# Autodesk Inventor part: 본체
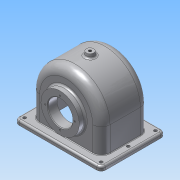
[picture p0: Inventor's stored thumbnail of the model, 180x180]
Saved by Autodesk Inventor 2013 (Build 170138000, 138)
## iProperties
Created: 2015-09
Part Number: 본체
Material: 알루미늄 6061
Document SubType Name: Modeling
Designer: Administrator
Density: 2.71 g/cm^3
Mass: 723.133 g
Surface Area: 889.936 cm^2
Volume: 266.839 cm^3
Author: Administrator
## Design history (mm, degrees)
sketch "스케치1"
  geometry: L1 (-52, 70)-(52, 70); L2 (52, 70)-(52, -70); L3 (52, -70)-(-52, -70); L4 (-52, -70)-(-52, 70); 3 further points
  constraints: 8 end point, 2 midpoint, 2 parallel, 1 horizontal, 1 horizontal alignment, 1 perpendicular, 1 vertical alignment
  dimensions: "d0" = 104 distance of L1.start L1.end; "d2" = 140 distance of L3.end L1.start
extrude "돌출1" new body sketch "스케치1" distance "d3" = 7; taper "d4" = 0 deg
sketch "스케치2" dims "d100" = 3
  geometry: L1 (70, 7)-(-70, 7) reference; L2 (-57, 7)-(-57, 47); L3 (57, 47)-(57, 7); L4 (-70, 0)-(70, 0) reference; A1 r 57 centre (0, 47) between (57, 47) and (-57, 47); 2 further points
  constraints: 4 end point, 2 perpendicular, 2 point on circle, 2 point on line, 2 tangent, 1 centre point, 1 midpoint, 1 vertical alignment
  dimensions: "d5" = 47 distance from line of L4 A1.centre; "d7" = 57 radius of A1
extrude "돌출2" join sketch "스케치2" stored distance "d8" = 77; taper "d9" = 0 deg
sketch "스케치7"
  geometry: L1 (-57, 7)-(-57, 47) reference; L2 (57, 47)-(57, 7) reference; L3 (-51, 7)-(-51, 47); L4 (51, 47)-(51, 7); L5 (-51, 7)-(-51, -13.982); L6 (-51, -13.982)-(51, -13.982); L7 (51, -13.982)-(51, 7); A1 r 57 centre (0, 47) between (57, 47) and (-57, 47) reference; A2 r 51 centre (0, 47) between (51, 47) and (-51, 47); 1 further point
  constraints: 10 end point, 2 point on circle, 1 centre point, 1 collinear, 1 parallel, 1 perpendicular, 2 other
  dimensions: "d21" = 6 distance between parallel lines of L1 L3
extrude "돌출5" cut sketch "스케치7" stored distance "d22" = 67; taper "d23" = 0 deg
sketch "스케치15"
  geometry: C1 r 31 at (47, 0); A1 r 57 centre (47, 0) between (47, -57) and (47, 57) reference; 1 further point
  constraints: 1 centre point, 1 coincident
  dimensions: "d52" = 62 diameter of C1
extrude "돌출7" join sketch "스케치15" distance "d54" = 10; taper "d55" = 0 deg
sketch "스케치18"
  geometry: L1 (33.5, 0)-(-33.5, 0) reference; L2 (-49.949, 47)-(14.472, 47); L3 (-33.5, 98)-(-33.5, 47) reference; L4 (-33.5, 86.747)-(-19.5, 75); L5 (-19.5, 75)-(-19.5, 47); L6 (-33.5, 86.747)-(-33.5, 47); L7 (-33.5, 47)-(-19.5, 47); 1 further point
  constraints: 10 end point, 2 parallel, 2 point on line, 1 perpendicular
  dimensions: "d70" = 47 distance between parallel lines of L1 L2; "d71" = 56 diameter of L4.end L2; "d72" = 50 deg angle of L4 L5; "d73" = 14 distance between parallel lines of L3 L5
revolve "회전3" sketch "스케치18" stored, may be unused: angle "d74" = 90 deg
sketch "스케치19"
  geometry: L1 (-33.5, 86.747)-(-19.5, 75) reference; L2 (-38.5, 84.416)-(-33.237, 80); L3 (-38.5, 104)-(-38.5, 47) reference; L4 (-38.5, 47)-(-19.5, 47); L5 (-19.5, 19)-(-19.5, 75) reference; L6 (-33.237, 80)-(-35.5, 80); L7 (-35.5, 80)-(-35.5, 47); L8 (-38.5, 84.416)-(-38.5, 47); L9 (-35.5, 47)-(-38.5, 47); 1 further point
  constraints: 12 end point, 3 perpendicular, 2 parallel, 2 point on line, 1 collinear, 1 midpoint
  dimensions: "d75" = 5 distance between parallel lines of L2 L1; "d76" = 3 distance between parallel lines of L3 L7; "d77" = 66 diameter of L6 L4
revolve "회전4" sketch "스케치19" stored, may be unused: angle "d78" = 90 deg
fillet "모깎기2" dims "d79" = 0.5
sketch "스케치20" dims "d80" = 56
  geometry: C1 r 33 at (0, 0) reference; 3 further points
  constraints: 2 vertical alignment, 1 coincident, 2 other
hole "구멍2" sketch "스케치20" at (0, 28) diameter "d82" = 2.459; stored, may be unused: countersink angle "d86" = 90 deg, drill point angle "d88" = 118 deg; dims "d83" = 7, "d84" = 4, "d85" = 2, "d87" = 9
hole "구멍1" diameter "d58" = 40; stored, may be unused: countersink angle "d62" = 90 deg, drill point angle "d64" = 0 deg; dims "d59" = 6, "d60" = 4, "d61" = 2, "d63" = 30, "d92" = 10, "d93" = 10
node "작업 평면1"
sketch "스케치21"
  geometry: C1 r 6 at (0, 0); 1 further point
  constraints: 1 centre point, 1 coincident
  dimensions: "d95" = 12 diameter of C1
extrude "돌출9" join sketch "스케치21" stored distance "d97" = 14; taper "d98" = 10 deg
fillet "모깎기4" dims "d100" = 3
hole "구멍3" diameter "d103" = 4.459; stored, may be unused: countersink angle "d107" = 90 deg, drill point angle "d109" = 118 deg; dims "d101" = 10, "d102" = 10, "d104" = 28, "d105" = 4, "d106" = 2, "d108" = 30
sketch "스케치22" dims "d110" = 48
  geometry: C1 r 20 at (0, 0) reference; 3 further points
  constraints: 2 vertical alignment, 1 coincident, 2 other
hole "구멍4" sketch "스케치22" at (0, 24) diameter "d112" = 2.621; stored, may be unused: countersink angle "d116" = 90 deg, drill point angle "d118" = 118 deg; dims "d113" = 6, "d114" = 4, "d115" = 2, "d117" = 8
sketch "스케치23"
  geometry: L1 (-13.5, 47)-(90.5, 47) reference; L2 (62.364, 13.623)-(14.636, 13.623); L3 (14.636, 13.623)-(14.636, 20.377); L4 (14.636, 20.377)-(62.364, 20.377); L5 (62.364, 20.377)-(62.364, 13.623); 5 further points
  constraints: 3 midpoint, 2 vertical alignment, 1 horizontal alignment, 2 other
  dimensions: "d122" = 30 distance from line of L1 point (38.5, 17)
feature "엠보싱1" sketch "스케치23" dims "d0" = 104, "d2" = 140, "d123" = 0.5, "d124" = 0
fillet "모깎기5" dims "d125" = 14
fillet "모깎기6" dims "d126" = 3
fillet "모깎기7" dims "d127" = 9
chamfer "모따기1" distance "d128" = 1; stored, may be unused: second distance "d129" = 2, angle "d130" = 45 deg
sketch "스케치24"
  geometry: L1 (-38.5, -43)-(-38.5, 43) reference; L2 (-24.5, 57)-(24.5, 57) reference; L3 (38.5, 43)-(38.5, -43) reference; L4 (24.5, -57)-(-24.5, -57) reference; L5 (52, 70)-(-52, 70) reference; L6 (-52, 70)-(-52, -70) reference; L7 (-52, -70)-(52, -70) reference; L8 (52, -70)-(52, 70) reference; A1 r 14 centre (-24.5, 43) between (-24.5, 57) and (-38.5, 43) reference; A2 r 14 centre (24.5, 43) between (38.5, 43) and (24.5, 57) reference; A3 r 14 centre (24.5, -43) between (24.5, -57) and (38.5, -43) reference; A4 r 14 centre (-24.5, -43) between (-38.5, -43) and (-24.5, -57) reference; 7 further points
  constraints: 4 horizontal alignment, 4 vertical alignment
  dimensions: "d136" = 8 distance from line of L8 point (44, -62); "d137" = 8 distance from line of L7 point (44, -62); "d138" = 124 distance of point (44, 62) point (44, -62); "d139" = 88 distance of point (-44, -62) point (44, -62)
hole "구멍5" sketch "스케치24" at (44, -62), (-44, -62), (-44, 62), (44, 62), (0, 62), (0, -62) diameter "d140" = 5; stored, may be unused: countersink angle "d144" = 90 deg, drill point angle "d146" = 118 deg; dims "d141" = 6, "d142" = 4, "d143" = 2, "d145" = 8
fillet "모깎기8" dims "d147" = 1
fillet "모깎기9" dims "d148" = 3
fillet "모깎기10" dims "d149" = 7
fillet "모깎기11" dims "d150" = 3
node "솔리드1"
pattern_circular "원형 패턴1" dims angle "d90" = 360 deg
pattern_circular "원형 패턴2" dims angle "d120" = 360 deg
node "투영된 루프2"
